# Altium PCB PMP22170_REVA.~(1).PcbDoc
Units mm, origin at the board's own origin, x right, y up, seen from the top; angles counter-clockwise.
Board outline 125.73 x 87.63 mm, 2 copper layers (Top Layer, Bottom Layer), stack 1.575 mm thick; 24 components, 0 nets, 16 pads, 0 vias.
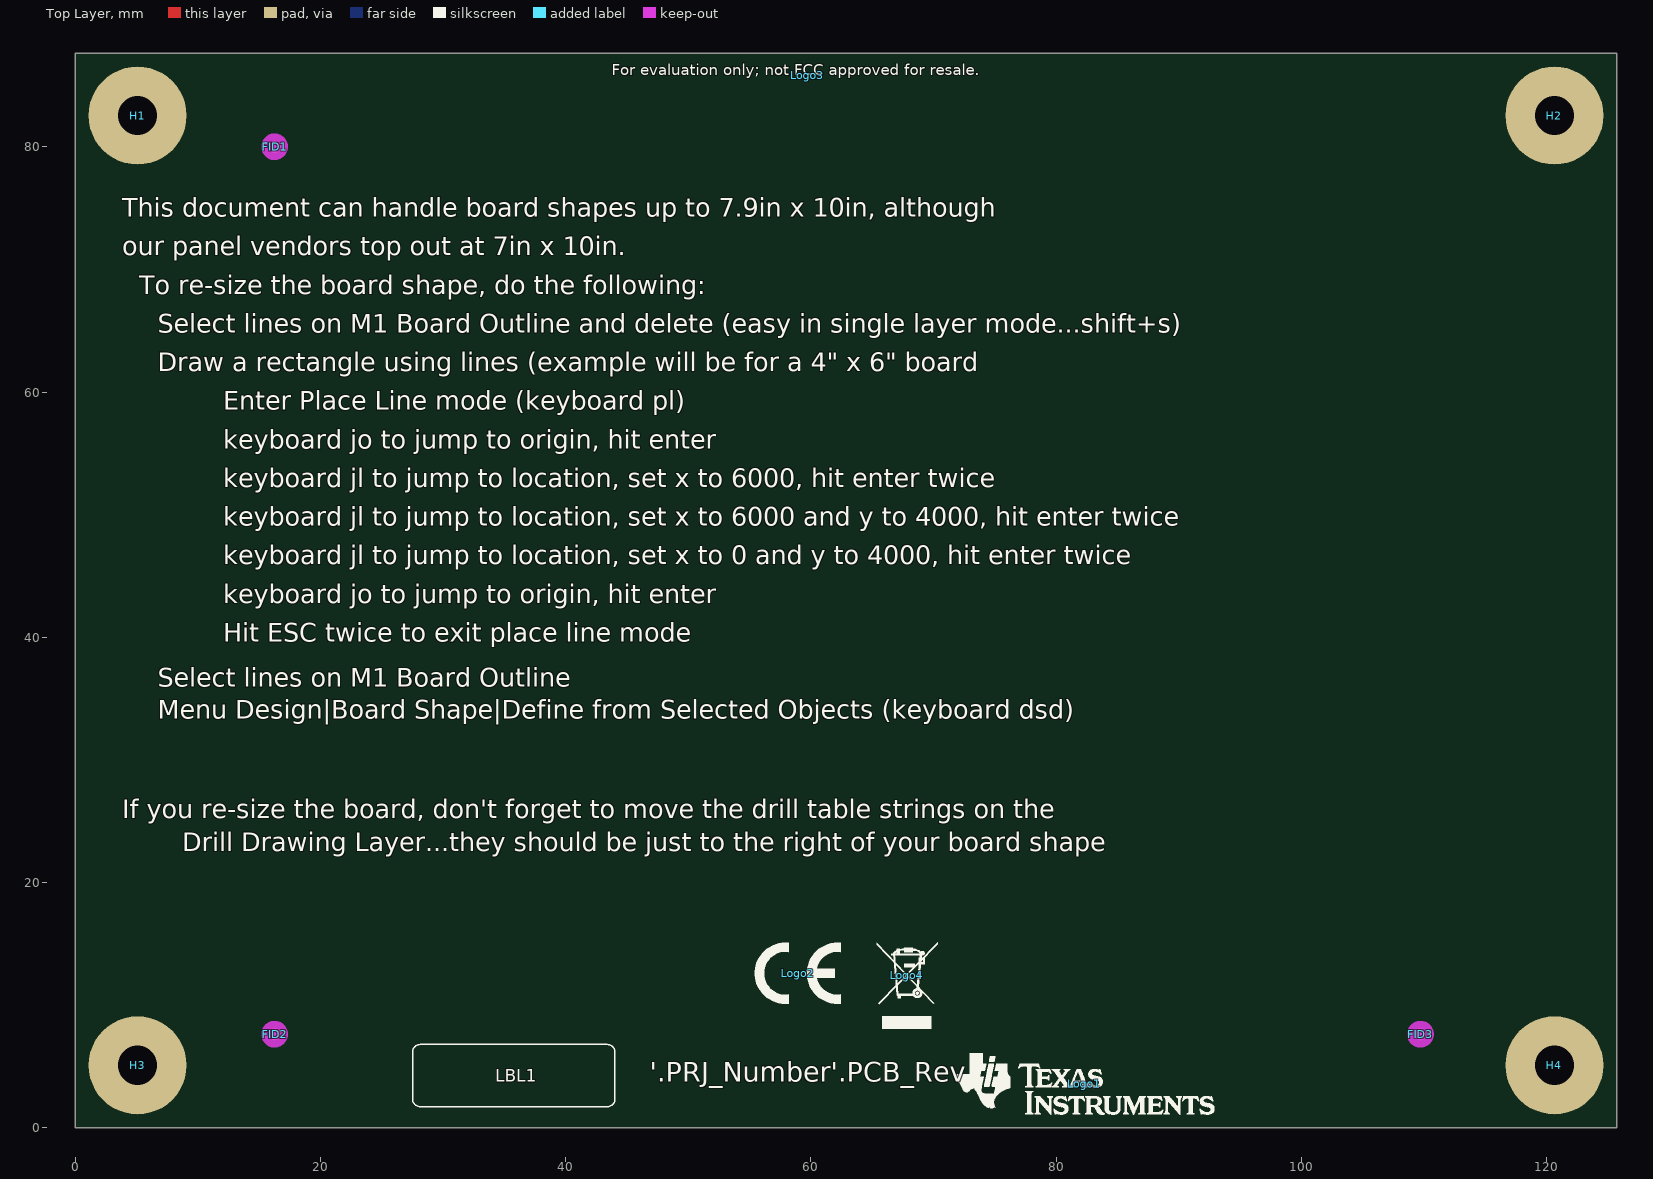
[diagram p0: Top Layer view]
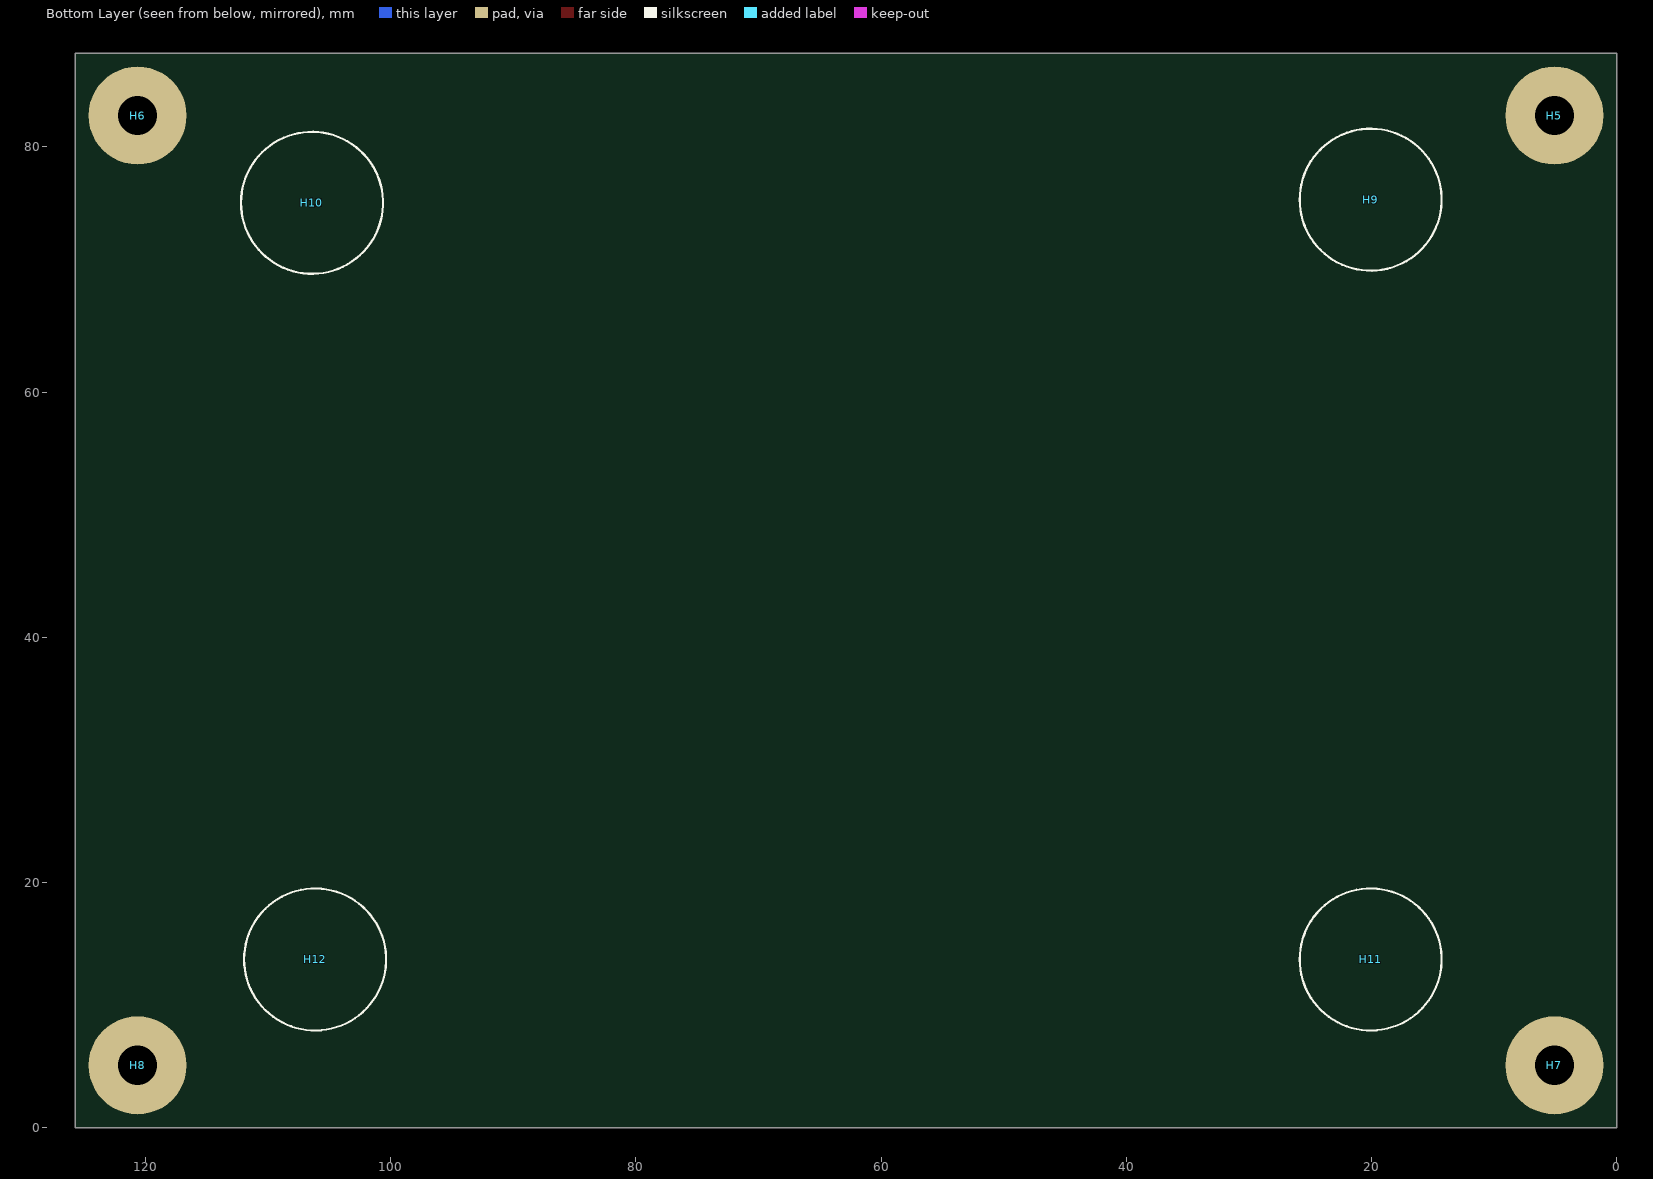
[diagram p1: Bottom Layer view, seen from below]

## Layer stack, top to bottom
Top Solder: solder mask 0.0102, Solder Resist, Dk 3.5
Top Layer: signal copper 0.0356
Dielectric1: core 1.5037, FR-4, Dk 4.8
Bottom Layer: signal copper 0.0356
Bottom Solder: solder mask 0.0102, Solder Resist, Dk 3.5

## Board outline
0,0 125.73,0 125.73,87.63 0,87.63

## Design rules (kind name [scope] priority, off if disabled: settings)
AcuteAngle [All] p1: minimum=4.50000000000000E+0001 checktracksonly=FALSE
AssemblyTestPointUsage [All] p1: valid=2
BoardOutlineClearance BoardOutlineClearance_MountingHoles [OnCopper and InComponentClass('Mounting Holes')] p1: gap=1 ignorepadtopadclearanceinfootprint=FALSE
BoardOutlineClearance BoardOutlineClearance_Poly [OnCopper and IsPoly] p2: gap=0.635 ignorepadtopadclearanceinfootprint=FALSE
BoardOutlineClearance [OnCopper and Not InComponentClass('Logo') and not InComponentClass('FiducialMark') and not InRegion(1000,500,4000,800) and not InPoly] p3: gap=1.905 ignorepadtopadclearanceinfootprint=FALSE
Clearance Clearance_Keepouts [((IsTrack Or IsArc) And Not InPoly) And IsFree and IsKeepOut vs ((IsTrack Or IsArc) And Not InPoly) And IsFree and IsKeepOut] p1: gap=0 ignorepadtopadclearanceinfootprint=FALSE
Clearance Clearance_Poly [InPolygon] p2: gap=0.635 ignorepadtopadclearanceinfootprint=TRUE
Clearance Clearance_FiducialMark [IsKeepOut and InComponentClass('FiducialMark') vs IsPad and InComponentClass('FiducialMark')] p3: gap=0 ignorepadtopadclearanceinfootprint=FALSE
Clearance [All] p4: gap=0.2 ignorepadtopadclearanceinfootprint=TRUE
ComponentClearance ComponentClearance_MountingHoles_FiducialMarks [InComponentClass('Mounting Holes') vs InComponentClass('FiducialMark')] p1: gap=1.27 collisioncheckmode=3 verticalgap=0.254 showdistances=FALSE
ComponentClearance ComponentClearance_Shunt [InComponentClass('Header') vs InComponentClass('Shunt')] p2: gap=0 collisioncheckmode=3 verticalgap=0 showdistances=FALSE
ComponentClearance ComponentClearance_Logo [InComponentClass('Logo')] p3: gap=1.27 collisioncheckmode=3 verticalgap=0.254 showdistances=FALSE
ComponentClearance ComponentClearance_ScrewToNut [(HasFootprint('NY PMS 440 0025 PH')) vs (HasFootprint('Keystone_1902C'))] p4: gap=0.127 collisioncheckmode=3 verticalgap=0.254 showdistances=FALSE
ComponentClearance ComponentClearance_MountingHoles [InComponentClass('Mounting Holes')] p5: gap=6.35 collisioncheckmode=3 verticalgap=2540 showdistances=FALSE
ComponentClearance ComponentClearance_SmallPassives [HasFootprint('0201*') or HasFootprint('0402*') or HasFootprint('0508') or HasFootprint('0603*') or HasFootprint('0612') or HasFootprint('0805*') or HasFootprint('0815*') or HasFootprint('0830*') or HasFootprint('1206*') or HasFootprint('1210*') or HasFootprint('1808*') or HasFootprint('1812*') or HasFootprint('1825*') or HasFootprint('2010*') or HasFootprint('2220*') or HasFootprint('2225*') or HasFootprint('2512*') or HasFootprint('2728*') or HasFootprint('3518*') vs HasFootprint('0201*') or HasFootprint('0402*') or HasFootprint('0508') or HasFootprint('0603*') or HasFootprint('0612') or HasFootprint('0805*') or HasFootprint('0815*') or HasFootprint('0830*') or HasFootprint('1206*') or HasFootprint('1210*') or HasFootprint('1808*') or HasFootprint('1812*') or HasFootprint('1825*') or HasFootprint('2010*') or HasFootprint('2220*') or HasFootprint('2225*') or HasFootprint('2512*') or HasFootprint('2728*') or HasFootprint('3518*')] p6: gap=0.38 collisioncheckmode=3 verticalgap=0.254 showdistances=FALSE
ComponentClearance ComponentClearance_THtoSMT [IsThruComponent vs IsSMTComponent] p7: gap=1.016 collisioncheckmode=3 verticalgap=0.762 showdistances=FALSE
ComponentClearance ComponentClearance_THtoTH [IsThruComponent vs IsThruComponent] p8: gap=0.762 collisioncheckmode=3 verticalgap=0.762 showdistances=FALSE
ComponentClearance [All] p9: gap=0.762 collisioncheckmode=3 verticalgap=0.254 showdistances=FALSE
DiffPairsRouting [All] p1: maxlimit=2.54 minlimit=0.254 mostfreqgap=0.254 toplayer_minwidth=0.381 toplayer_maxwidth=0.381 toplayer_prefwidth=0.381 bottomlayer_minwidth=0.381 bottomlayer_maxwidth=0.381 bottomlayer_prefwidth=0.381 maxuncoupledlength=25.4
FabricationTestPointUsage TestPointUsage [All] p1: valid=2 allowmultiple=FALSE
FabricationTestpoint Testpoint [All] p1: side=3 testpointundercomponent=TRUE minsize=1.016 maxsize=2.54 preferedsize=1.524 minholesize=0 maxholesize=1.016 preferedholesize=0.813 testpointgrid=0.025 allowsidetop=TRUE allowsidebottom=TRUE usegrid=TRUE gridtolerance=0
FanoutControl Fanout_LCC [IsLCC] p1: bgadir=Out bgaviamode=Centered fanoutstyle=Auto fanoutdirection=Alternating viagrid=0.025 // Fanout_LCC (Default Rule)
FanoutControl Fanout_BGA [IsBGA] p2: bgadir=Out bgaviamode=Centered fanoutstyle=Auto fanoutdirection=Alternating viagrid=0.025 // Fanout_BGA (Default Rule)
FanoutControl Fanout_Default [All] p4: bgadir=Out bgaviamode=Centered fanoutstyle=Auto fanoutdirection=Alternating viagrid=0.025 // Fanout_Default (Default Rule)
FanoutControl Fanout_Small [(CompPinCount < 5)] p5: bgadir=Out bgaviamode=Centered fanoutstyle=Auto fanoutdirection=OutThenIn viagrid=0.025 // Fanout_Small (Default Rule)
HoleSize [All] p1: absolutevalues=TRUE maxlimit=6.375 minlimit=0.2 maxpercent=80.000 minpercent=20.000
MinimumAnnularRing MinimumAnnularRing_ThermalPadVias [IsVia and InAnyComponent] p1: minimumring=0.15
MinimumAnnularRing [All] p2: minimumring=0.2
MinimumSolderMaskSliver MinimumSolderMaskSliver_Logo [InComponentClass('Logo') vs InComponentClass('Logo')] p1: minsoldermaskwidth=0.018
MinimumSolderMaskSliver [All] p2: minsoldermaskwidth=0.1
PlaneConnect [All] p1: planeconnectstyle=Relief reliefexpansion=0.254 reliefentries=4 reliefconductorwidth=0.254 reliefairgap=0.254
PolygonConnect [All] p1: connectstyle=Relief reliefconductorwidth=0.254 reliefentries=4 polygonreliefangle="90 Angle" airgapwidth=0.254
RoutingVias ThermalPadVias [IsVia and InAnyComponent] p1: holewidth=0.2 width=0.5 viastyle="Through Hole" minholewidth=0.2 minwidth=0.5 maxholewidth=0.33 maxwidth=0.6
RoutingVias [All] p2: holewidth=0.406 width=0.864 viastyle="Through Hole" minholewidth=0.2 minwidth=0.66 maxholewidth=1.016 maxwidth=1.651
SilkToBoardRegionClearance [Not ((IsComment or IsDesignator) And (Hide <> 'False')) and not InRegion(1000,500,4000,800)] p1:
SilkToSilkClearance SilkToSilkClearance_Pb-FreeLogo [(HasFootprint('Pb-Free_Overlay_Medium') OR HasFootprint('Pb-Free_Overlay_Small')) vs (HasFootprint('Pb-Free_Overlay_Medium') OR HasFootprint('Pb-Free_Overlay_Small'))] p1: silktosilkclearance=0
SilkToSilkClearance [All] p2: silktosilkclearance=0.1
SilkToSolderMaskClearance SilkToComponentPadClearance [(IsPad or IsFill or IsRegion) and InAnycomponent] p1: minsilkscreentomaskgap=0.127 clearancetoexposedcopper=TRUE
SilkToSolderMaskClearance "Silk to Solder Mask Opening" [All] p2: minsilkscreentomaskgap=0.1 clearancetoexposedcopper=FALSE
SolderMaskExpansion [All] p1: expansion=0.05
UnRoutedNet [All] p1: checkbadconnections=TRUE
Width [All] p1: maxlimit=2.54 minlimit=0.152 preferedwidth=0.254 checkconnectedcopper=TRUE
14 further rules are at their usual default settings.

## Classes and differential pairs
component class "Mounting Holes": H1 H2 H3 H4
component class Logo: Logo1
component class FiducialMark: FID1 FID2 FID3
component class AssemblyNote: ZZ1 ZZ2 ZZ3 ZZ4
component class Label: LBL1

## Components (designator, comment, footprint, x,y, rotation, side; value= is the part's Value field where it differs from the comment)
FID1 "Fiducial" Fiducial10-20 16.256,80.01 r0 top
FID2 "Fiducial" Fiducial10-20 16.256,7.62 r0 top
FID3 "Fiducial" Fiducial10-20 109.728,7.62 r0 top
H1 "NY PMS 440 0025 PH" "NY PMS 440 0025 PH" 5.08,82.55 r0 top locked
H2 "NY PMS 440 0025 PH" "NY PMS 440 0025 PH" 120.65,82.55 r0 top locked
H3 "NY PMS 440 0025 PH" "NY PMS 440 0025 PH" 5.08,5.08 r0 top locked
H4 "NY PMS 440 0025 PH" "NY PMS 440 0025 PH" 120.65,5.08 r0 top locked
H5 "1902C" Keystone_1902C 5.08,82.55 r180 bottom locked
H6 "1902C" Keystone_1902C 120.65,82.55 r180 bottom locked
H7 "1902C" Keystone_1902C 5.08,5.08 r180 bottom locked
H8 "1902C" Keystone_1902C 120.65,5.08 r180 bottom locked
H9 "SJ-5303 (CLEAR)" Bumpon_SJ5003Transparent 20.066,75.692 r180 bottom
H10 "SJ-5303 (CLEAR)" Bumpon_SJ5003Transparent 106.426,75.438 r180 bottom
H11 "SJ-5303 (CLEAR)" Bumpon_SJ5003Transparent 20.066,13.716 r180 bottom
H12 "SJ-5303 (CLEAR)" Bumpon_SJ5003Transparent 106.172,13.716 r180 bottom
LBL1 "THT-14-423-10" Label_650x200 35.763,4.242 r0 top
Logo1 "Texas Instruments" TI_Stacked_Overlay_Small 82.296,3.556 r0 top
Logo2 "CE Mark" CE_Mark_5mm 58.928,12.59 r0 top
Logo3 "FCC disclaimer" FCC_disclaimer 59.69,85.852 r0 top
Logo4 "WEEE logo" WEEE_Minimum 67.818,12.446 r0 top
ZZ1 "This Assembly Note is for PCB labels only" AssemblyNoteLabel 4.699,100.025 r0 top
ZZ2 "These assemblies are ESD sensitive, ESD precautions shall be observed." AssemblyNote 4.699,97.259 r0 top
ZZ3 "These assemblies must be clean and free from flux and all contaminants. Use of no clean flux is not acceptable." AssemblyNote 4.699,95.01 r0 top
ZZ4 "These assemblies must comply with workmanship standards IPC-A-610 Class 2, unless otherwise specified." AssemblyNote 4.699,92.761 r0 top

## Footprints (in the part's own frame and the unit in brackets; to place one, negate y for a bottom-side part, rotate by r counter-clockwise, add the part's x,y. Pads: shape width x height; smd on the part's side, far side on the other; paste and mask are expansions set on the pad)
AssemblyNote [mm] "Assembly Note"
AssemblyNoteLabel [mm] "Assembly Note for PCB Labels"
Bumpon_SJ5003Transparent [mil] "3M Hemispherical Bumpon transparent"
  round 1 on Mech4: 0(0,0)
  silkscreen extent -228,-228 228,228, body extent -219,-219 219,219, height 197
CE_Mark_5mm [mm] "Minimum text height for CE Mark"
  silkscreen extent -3.5,-2.5 3.5,2.5
FCC_disclaimer [mm]
Fiducial10-20 [mm]
  round 1 smd mask+0.5: 1(0,0)
  Top Layer keep-out circle w1.178: c0,0 r0.5
Keystone_1902C [mil] "Hex Standoff, 4-40 threaded, nylon"
  round 1 on Mech4: 0(0,0)
  body extent -145,-126 146,126, height 501
Label_650x200 [mil] "Thermal Transfer Label"
  round 1 on Mech13: 0(0,0)
  silkscreen extent -325,-100 325,100, body extent -325,-100 325,100, height 1
"NY PMS 440 0025 PH" [mm] "4-40 nylon screw and mounting hole"
  round 8 hole 3.2: 1(0,0)
  body extent -3.3,-3.3 3.3,3.3, height 2.69
TI_Stacked_Overlay_Small [mm]
  silkscreen extent -10.63,-2.49 10.63,2.49
WEEE_Minimum [mm] "WEEElie bin"
  silkscreen extent -2.42,-4.38 2.52,2.65

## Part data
FID1 FID2 FID3: library part CMP-0077181-1, "Fiducial mark.  There is nothing to buy or mount.", Manufacturer=N/A
H1 H2 H3 H4: library part CMP-0003617-1, "Machine Screw, Round, #4-40 x 1/4, Nylon, Philips panhead", Manufacturer="B&F Fastener Supply", Supplier Part Number 1=H542-ND
H5 H6 H7 H8: library part CMP-0003610-1, "Standoff, Hex, 0.5\"L #4-40 Nylon", Manufacturer=Keystone, Supplier Part Number 1=36-1902C-ND
H9 H10 H11 H12: library part CMP-0003620-1, "Bumpon, Hemisphere, 0.44 X 0.20, Clear", Manufacturer=3M, Supplier Part Number 1=SJ5303-7-ND
LBL1: library part CMP-0003625-1, "Thermal Transfer Printable Labels, 0.650\" W x 0.200\" H - 10,000 per roll", Manufacturer=Brady, Supplier Part Number 1=97C5133
Logo1: library part CMP-0074838-1, "Texas Instrument Corporate Signature"
Logo2: library part CMP-0074844-1
Logo3: library part CMP-0074847-1, "FCC_disclaimer"
Logo4: library part CMP-0074769-1
ZZ1: library part CMP-0003616-3
ZZ2: library part CMP-0077236-1
ZZ3: library part CMP-0077237-1
ZZ4: library part CMP-0077238-1

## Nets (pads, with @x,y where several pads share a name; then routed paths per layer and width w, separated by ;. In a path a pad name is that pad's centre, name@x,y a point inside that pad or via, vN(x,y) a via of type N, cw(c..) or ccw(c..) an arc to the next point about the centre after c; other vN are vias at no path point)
pads on no net: FID1.1 FID2.1 FID3.1 H1.1 H2.1 H3.1 H4.1 H5.0 H6.0 H7.0 H8.0 H9.0 H10.0 H11.0 H12.0 LBL1.0

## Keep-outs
Keep-Out Layer:
  text ".Layer_Name" at 14.656,-21.806 h1.52

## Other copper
Top Layer:
  text ".Layer_Name" at 14.656,-21.806 h1.52
Bottom Layer:
  text ".Layer_Name" at 14.656,-21.806 h1.52

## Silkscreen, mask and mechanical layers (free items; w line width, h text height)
Top Overlay:
  text "This document can handle board shapes up to 7.9in x 10in, although" at 3.81,74.295 h1.52
  text "our panel vendors top out at 7in x 10in." at 3.81,71.144 h1.52
  text "To re-size the board shape, do the following:" at 5.207,67.993 h1.52
  text "Select lines on M1 Board Outline and delete (easy in single layer mode...shift+s)" at 6.731,64.842 h1.52
  text "Draw a rectangle using lines (example will be for a 4\" x 6\" board" at 6.731,61.691 h1.52
  text "Enter Place Line mode (keyboard pl)" at 12.065,58.54 h1.52
  text "keyboard jo to jump to origin, hit enter" at 12.065,55.388 h1.52
  text "keyboard jl to jump to location, set x to 6000, hit enter twice" at 12.065,52.237 h1.52
  text "keyboard jl to jump to location, set x to 6000 and y to 4000, hit enter twice" at 12.065,49.086 h1.52
  text "keyboard jl to jump to location, set x to 0 and y to 4000, hit enter twice" at 12.065,45.935 h1.52
  text "keyboard jo to jump to origin, hit enter" at 12.065,42.784 h1.52
  text "Hit ESC twice to exit place line mode" at 12.065,39.633 h1.52
  text "Select lines on M1 Board Outline" at 6.731,35.974 h1.52
  text "Menu Design|Board Shape|Define from Selected Objects (keyboard dsd)" at 6.731,33.331 h1.52
  text "If you re-size the board, don't forget to move the drill table strings on the" at 3.81,25.222 h1.52
  text "Drill Drawing Layer...they should be just to the right of your board shape" at 8.712,22.53 h1.52
  text "'.PRJ_Number'.PCB_Rev" at 46.863,3.195 h2.75
  text ".Layer_Name" at 14.656,-21.806 h1.52
Bottom Overlay:
  text ".Layer_Name" at 14.656,-21.806 h1.52
Top Paste:
  text ".Layer_Name" at 14.656,-21.806 h1.52
Bottom Paste:
  text ".Layer_Name" at 14.656,-21.806 h1.52
Top Solder:
  text ".Layer_Name" at 14.656,-21.806 h1.52
  text ".Layer_Name" at 14.656,-21.806 h1.52
Bottom Solder:
  text ".Layer_Name" at 14.656,-21.806 h1.52
Drill Guide:
  text ".Layer_Name" at 14.656,-21.806 h1.52
M1 Board Outline:
  the board outline again, w0.254
  text ".Layer_Name" at 14.656,-21.806 h1.52
M2 Board Dimensions:
  rectangle: 0,-6.985 3.175,-3.81
  rectangle: 3.175,-10.16 12.7,-6.985
  lines w0.178: 0,-6.985 25.4,-6.985 ; 3.175,-10.16 3.175,-3.81 ; 6.35,-10.16 6.35,-3.81 ; 12.7,-10.16 12.7,-3.81 ; 19.05,-10.16 19.05,-3.81 ; 0,-10.16 25.4,-10.16 25.4,-3.81 0,-3.81 0,-10.16
  text ".Layer_Name" at 14.656,-21.806 h1.52
M3 3D STEP Top:
  text ".Layer_Name" at 14.656,-21.806 h1.52
M4 3D STEP Bottom:
  text ".Layer_Name" at 14.656,-21.806 h1.52
M5 Assembly Top:
  lines w0.254: -7.417,-23.626 160.223,-23.626 ; -7.417,-18.462 160.274,-18.462 ; -7.417,-13.297 -7.417,-28.791 94.31,-28.791 160.274,-28.791 160.274,-13.297 -7.404,-13.297 -7.404,-28.791 32.614,-28.791 ; 55.194,-28.791 55.194,-13.297 ; 87.376,-18.462 87.376,-13.297 ; 108.712,-18.462 108.712,-13.297 ; 124.511,-28.956 124.511,-23.804
  text "COMPONENTS MARKED 'DNP' SHOULD NOT BE POPULATED." at 29.299,-8.09 h1.52
  text "ASSEMBLY VARIANT:" at 29.286,-11.024 h1.52
  text ".VariantName" at 55.601,-11.024 h1.52
  text "PCB VIEWED FROM TOP SIDE" at -5.804,-16.654 h1.52
  text "BOARD #:" at 57.099,-16.654 h1.52
  text ".PRJ_Number" at 70.955,-16.654 h1.52
  text "REV:" at 92.405,-16.654 h1.52
  text ".PCB_Rev" at 99.809,-16.654 h1.52
  text "SVN REV:" at 113.69,-16.654 h1.52
  text ".VersionControl_RevNumber" at 126.543,-16.654 h1.52
  text "TID #:" at 57.099,-21.819 h1.52
  text ".TID" at 70.955,-21.819 h1.52
  text "PLOT NAME =" at -5.804,-27.034 h1.52
  text ".plot_File_Name" at 14.656,-27.034 h1.52
  text "GENERATED    :" at 57.15,-27.034 h1.52
  text ".Print_Date" at 79.235,-27.034 h1.52
  text ".Print_Time" at 97.752,-27.034 h1.52
  text "TEXAS INSTRUMENTS" at 129.87,-27.034 h1.52
M6 Assembly Bottom:
  lines w0.254: -7.429,-18.474 160.261,-18.474 ; -7.379,-23.639 160.261,-23.639 ; 28.334,-28.969 28.334,-23.817 ; 44.133,-18.474 44.133,-13.31 ; 65.468,-18.474 65.468,-13.31 ; 97.65,-28.804 97.65,-13.31 ; 120.231,-28.804 160.249,-28.804 160.249,-13.31 -7.429,-13.31 -7.429,-28.804 58.534,-28.804 160.261,-28.804 160.261,-13.31
  text "COMPONENTS MARKED 'DNP' SHOULD NOT BE POPULATED." at 154.991,-8.077 h1.52
  text ".VariantName" at 128.473,-11.024 h1.52
  text "ASSEMBLY VARIANT:" at 154.864,-11.024 h1.52
  text ".VersionControl_RevNumber" at 26.302,-16.667 h1.52
  text "SVN REV:" at 39.154,-16.667 h1.52
  text ".PCB_Rev" at 53.035,-16.667 h1.52
  text "REV:" at 60.439,-16.667 h1.52
  text ".PRJ_Number" at 81.89,-16.667 h1.52
  text "BOARD #:" at 95.745,-16.667 h1.52
  text "PCB VIEWED FROM BOTTOM SIDE" at 158.648,-16.667 h1.52
  text ".TID" at 81.89,-21.831 h1.52
  text "TID #:" at 95.745,-21.831 h1.52
  text "TEXAS INSTRUMENTS" at 22.974,-27.047 h1.52
  text ".Print_Time" at 55.093,-27.047 h1.52
  text ".Print_Date" at 73.609,-27.047 h1.52
  text "GENERATED    :" at 95.694,-27.047 h1.52
  text ".plot_File_Name" at 138.189,-27.047 h1.52
  text "PLOT NAME =" at 158.648,-27.047 h1.52
M9 Title Sheet:
  drawing of 57 lines, arcs and shapes, not listed
  text "1" at 18.792,204.127 h1.78
  text "2" at 82.182,204.127 h1.78
  text "3" at 145.411,204.127 h1.78
  text "4" at 209.08,204.127 h1.78
  text "5" at 272.555,204.127 h1.78
  text "6" at 336.182,204.127 h1.78
  text "A" at -10.579,175.095 h1.78
  text "A" at 365.341,175.095 h1.78
  text "B" at -10.579,114.643 h1.78
  text "B" at 365.341,114.643 h1.78
  text "C" at -10.579,54.318 h1.78
  text "C" at 365.341,54.318 h1.78
  text "PROJECT TITLE:" at 288.125,7.048 h1.14
  text ".PRJ_Title" at 289.395,3.662 h1.78
  text "DESIGNED FOR:" at 288.125,-0.597 h1.14
  text ".PRJ_Customer" at 289.395,-4.153 h1.78
  text "D" at -10.579,-5.88 h1.78
  text "D" at 365.341,-5.88 h1.78
  text "FILE NAME:" at 288.125,-8.217 h1.14
  text ".PCB_File_Name_No_Path" at 289.395,-11.265 h1.78
  text "Texas Instruments (TI) and/or its licensors do not warrant the accuracy or completeness of this specification" at 161.9,-15.376 h1.14
  text "ENGINEER:" at 288.125,-15.583 h1.14
  text "LAYOUT BY:" at 326.352,-15.583 h1.14
  text "or any information contained therein. TI and/or its licensors do not warrant that this design will meet" at 160.757,-18.237 h1.14
  text ".PRJ_Engineer" at 289.395,-19.52 h1.78
  text ".PCB_Layout" at 327.635,-19.52 h1.78
  text "the specifications, will be suitable for your application or fit for any particular purpose, or will operate in" at 160.757,-21.099 h1.14
  text ".Layer_Name" at 14.656,-21.806 h1.52
  text "ALTIUM DESIGNER VERSION:" at 326.352,-23.457 h1.14
  text "an implementation. TI and/or its licensors do not warrant that the design is production worthy. You should" at 160.757,-23.961 h1.14
  text "completely validate and test your design implementation to confirm the system functionality for your application." at 161.9,-26.822 h1.14
  text ".print_Scale" at 289.395,-26.843 h1.78
  text ".Application_BuildNumber" at 327.635,-26.843 h1.78
  text "1" at 18.792,-32.093 h1.78
  text "2" at 82.182,-32.093 h1.78
  text "3" at 145.411,-32.093 h1.78
  text "4" at 209.08,-32.093 h1.78
  text "5" at 272.555,-32.093 h1.78
  text "6" at 336.182,-32.093 h1.78
M10 Fab Notes:
  drawing of 189 lines, arcs and shapes, not listed
  text "DESIGN INFORMATION" at 314.503,161.447 h1.52
  text "MIN. TRACK WIDTH:" at 298.131,158.091 h1.52
  text "8" at 325.976,158.091 h1.52
  text "MIL" at 329.907,158.091 h1.52
  text "MIN. CLEARANCE:" at 298.131,154.938 h1.52
  text "0.2" at 324.452,154.938 h1.52
  text "mm" at 329.907,154.938 h1.52
  text "MIN. VIA PAD SIZE:" at 298.131,151.785 h1.52
  text "24" at 325.214,151.785 h1.52
  text "MIL" at 329.907,151.785 h1.52
  text "0.05mm (2MIL)" at 315.784,148.486 h1.52
  text "MINIMUM ANNULAR RING" at 289.769,148.277 h1.52
  text "EXTERNAL" at 333.768,148.277 h1.52
  text "PER" at 294.849,145.48 h1.52
  text "IPC-D-275 CLASS 2 LEVEL C" at 300.437,145.48 h1.52
  text "MIL, HOLES" at 338.238,142.928 h1.52
  text "+/-" at 328.27,142.709 h1.52
  text "+/-" at 349.961,142.709 h1.52
  text "REGISTRATION TOLERANCES:" at 289.769,142.682 h1.52
  text "METAL" at 320.243,142.682 h1.52
  text "5" at 334.879,142.683 h1.52
  text "3" at 356.037,142.683 h1.52
  text "MIL" at 358.99,142.682 h1.52
  text "HOLE SIZE TOLERANCE (UNLESS OTHERWISE SPECIFIED):" at 289.769,140.185 h1.52
  text "+/-" at 349.961,140.112 h1.52
  text "3" at 356.037,140.085 h1.52
  text "MIL" at 358.99,140.085 h1.52
  text "MATERIAL:" at 287.87,136.589 h1.52
  text "FR-4 High Tg" at 312.926,133.324 h1.52
  text "X" at 309.257,133.122 h1.52
  text "FR-408" at 298.563,133.007 h1.52
  text "OTHER" at 336.358,133.007 h1.52
  text "62 MIL (1.6mm) +/-10%" at 306.694,129.374 h1.52
  text "X" at 303.643,129.312 h1.52
  text "THICKNESS:" at 289.769,129.165 h1.52
  text "OTHER" at 339.33,129.165 h1.52
  text "TOLERANCE:" at 289.769,125.652 h1.52
  text "X" at 311.314,125.652 h1.52
  text "ANSI IPC-6012 TYPE 3 CLASS 2" at 315.836,125.652 h1.52
  text "OTHER +/-" at 315.835,121.989 h1.52
  text "BOW & TWIST:" at 289.769,118.302 h1.52
  text "X" at 311.314,118.302 h1.52
  text "ANSI IPC-6012 TYPE 3 CLASS 2" at 315.836,118.302 h1.52
  text "OTHER +/-" at 315.835,114.576 h1.52
  text "DRILLING:" at 287.87,111.258 h1.52
  text "NC_DRILL FILES" at 332.599,108.586 h1.52
  text "REFERENCE:" at 289.769,108.486 h1.52
  text "X" at 306.463,108.484 h1.52
  text "AS SHOWN" at 310.984,108.486 h1.52
  text "X" at 329.348,108.486 h1.52
  text "OTHER" at 340.168,104.873 h1.52
  text "PTH COPPER THICKNESS:" at 289.761,104.783 h1.52
  text "X" at 318.697,104.783 h1.52
  text "20-30 um" at 321.948,104.783 h1.52
  text "BOARD FINISH:" at 287.87,101.034 h1.52
  text "SILKSCREEN:" at 291.812,98.237 h1.52
  text "X" at 316.14,98.237 h1.52
  text "TOP" at 319.112,98.237 h1.52
  text "X" at 329.094,98.237 h1.52
  text "BOTTOM" at 332.091,98.237 h1.52
  text "SILKSCREEN COLOR:" at 291.812,94.295 h1.52
  text "X" at 316.115,94.295 h1.52
  text "WHITE" at 319.112,94.295 h1.52
  text "OTHER" at 332.091,94.295 h1.52
  text "X" at 319.442,90.652 h1.52
  text "GREEN" at 322.439,90.652 h1.52
  text "OTHER" at 338.136,90.652 h1.52
  text "SOLDER RESIST COLOR:" at 291.812,90.477 h1.52
  text "X" at 319.442,86.734 h1.52
  text "MATTE" at 322.439,86.734 h1.52
  text "SEMI-GLOSS" at 338.125,86.717 h1.52
  text "IMMERSION GOLD (ENIG)" at 314.819,82.345 h1.52
  text "ENEPIG" at 348.793,82.162 h1.52
  text "SURFACE FINISH:" at 287.87,82.136 h1.52
  text "X" at 310.298,82.136 h1.52
  text "IMM. TIN/SILVER OR EQUIV" at 296.24,78.649 h1.52
  text "OTHER" at 332.599,78.549 h1.52
  text "ARRAY/PANEL:" at 287.87,74.602 h1.52
  text "CUT AND TRIM PER M1 BOARD OUTLINE" at 314.819,74.393 h1.52
  text "N.C. ROUTE" at 314.819,70.94 h1.52
  text "X" at 332.295,70.94 h1.52
  text "V. SCORE" at 336.816,70.94 h1.52
  text "CERTIFICATION:" at 287.87,67.66 h1.52
  text "MATERIALS AND WORKMANSHIP FOR ALL PCBS" at 306.285,67.66 h1.52
  text "TO MEET OR EXCEED THE REQUIREMENTS OF:" at 306.285,65.271 h1.52
  text "X" at 297.078,62.003 h1.52
  text "ANSI IPC-A-600F CLASS ->" at 300.329,62.003 h1.52
  text "X" at 342.188,62.003 h1.52
  text "2" at 344.982,62.003 h1.52
  text "1" at 336.981,61.965 h1.52
  text "3" at 353.973,61.965 h1.52
  text "X" at 317.702,58.252 h1.52
  text "RoHS" at 320.953,58.252 h1.52
  text "OTHER" at 337.321,58.252 h1.52
  text "PER ORDER" at 347.407,58.252 h1.52
  text "ALL BOARDS MUST MEET OR EXCEED UL94-V0 REQUIREMENTS." at 288.569,54.345 h1.52
  text "PCB MUST BEAR THE UL94V-0 UL REGISTERED MATERIAL ID NUMBER" at 288.569,51.397 h1.52
  text "ADDITIONAL REQUIREMENTS:" at 287.87,47.094 h1.52
  text "MICROSECTION:" at 289.769,44.373 h1.52
  text "YES" at 312.775,44.373 h1.52
  text "REQUIRED" at 334.657,40.707 h1.52
  text "BARE BOARD ELEC. TEST:" at 289.769,40.634 h1.52
  text "NONE" at 322.935,40.634 h1.52
  text "X" at 331.66,40.634 h1.52
  text "PER ORDER" at 349.693,40.634 h1.52
  text "XX MIL VIAS REQUIRE NON-CONDUCTIVE FILL AND PLANARIZE" at 294.04,35.428 h1.5
  text "XX MIL VIAS REQUIRE CONDUCTIVE FILL AND PLANARIZE" at 294.243,32.787 h1.52
  text "OUTER XX MIL TRACES REQUIRE 50 OHM SINGLE-ENDED IMPEDANCE" at 294.218,28.637 h1.47
  text "LAYER 2 & 3 (INNER LAYERS) XX MIL WIDE, XX MIL SPACE / TRACES REQUIRE 100 OHM DIFFERENTIAL IMPEDANCE" at 294.015,22.65 h1.52
  text ".Layer_Name" at 14.656,-21.806 h1.52
M11 Gerber Information:
  lines w0.254: -7.417,-23.626 160.223,-23.626 ; -7.417,-18.462 160.274,-18.462 ; -7.417,-13.297 -7.417,-28.791 94.31,-28.791 160.274,-28.791 160.274,-13.297 -7.404,-13.297 -7.404,-28.791 32.614,-28.791 ; 55.194,-28.791 55.194,-13.297 ; 87.376,-18.462 87.376,-13.297 ; 108.712,-18.462 108.712,-13.297 ; 124.511,-28.956 124.511,-23.804
  text "ALL ARTWORK VIEWED FROM TOP SIDE" at -5.804,-16.654 h1.52
  text "BOARD #:" at 57.099,-16.654 h1.52
  text ".PRJ_Number" at 70.955,-16.654 h1.52
  text "REV:" at 92.405,-16.654 h1.52
  text ".PCB_Rev" at 99.809,-16.654 h1.52
  text "SVN REV:" at 113.69,-16.654 h1.52
  text ".VersionControl_RevNumber" at 126.543,-16.654 h1.52
  text "LAYER NAME =" at -5.804,-21.806 h1.52
  text "TID #:" at 57.099,-21.819 h1.52
  text ".TID" at 70.955,-21.819 h1.52
  text "PLOT NAME =" at -5.804,-27.034 h1.52
  text ".plot_File_Name" at 14.656,-27.034 h1.52
  text "GENERATED    :" at 57.15,-27.034 h1.52
  text ".Print_Date" at 79.235,-27.034 h1.52
  text ".Print_Time" at 97.752,-27.034 h1.52
  text "TEXAS INSTRUMENTS" at 129.87,-27.034 h1.52
M12 Stackup:
  drawing of 191 lines, arcs and shapes, not listed
  text "Layer" at 249.215,199.452 h1.52
  text "Name" at 259.626,199.452 h1.52
  text "Material" at 283.242,199.452 h1.52
  text "Thickness" at 305.08,199.452 h1.52
  text "Constant" at 321.586,199.452 h1.52
  text "Board Layer Stack" at 336.06,199.452 h1.52
  text "1" at 249.215,196.404 h1.52
  text "Top Overlay" at 259.626,196.404 h1.52
  text "2" at 249.215,193.356 h1.52
  text "Top Solder" at 259.626,193.356 h1.52
  text "Solder Resist" at 283.242,193.356 h1.52
  text "0.40mil" at 305.08,193.356 h1.52
  text "3.5" at 321.586,193.356 h1.52
  text "3" at 249.215,190.308 h1.52
  text "Top Layer" at 259.626,190.308 h1.52
  text "Copper" at 283.242,190.308 h1.52
  text "1.40mil" at 305.08,190.308 h1.52
  text "4" at 249.215,187.26 h1.52
  text "Dielectric1" at 259.626,187.26 h1.52
  text "FR-4" at 283.242,187.26 h1.52
  text "59.20mil" at 305.08,187.26 h1.52
  text "4.8" at 321.586,187.26 h1.52
  text "5" at 249.215,184.212 h1.52
  text "Bottom Layer" at 259.626,184.212 h1.52
  text "Copper" at 283.242,184.212 h1.52
  text "1.40mil" at 305.08,184.212 h1.52
  text "6" at 249.215,181.164 h1.52
  text "Bottom Solder" at 259.626,181.164 h1.52
  text "Solder Resist" at 283.242,181.164 h1.52
  text "0.40mil" at 305.08,181.164 h1.52
  text "3.5" at 321.586,181.164 h1.52
  text "7" at 249.215,178.116 h1.52
  text "Bottom Overlay" at 259.626,178.116 h1.52
  text ".Layer_Name" at 14.656,-21.806 h1.52
M13 Component Bodies Top:
  text ".Layer_Name" at 14.656,-21.806 h1.52
M14 Component Bodies Bottom:
  text ".Layer_Name" at 14.656,-21.806 h1.52
M15 Courtyards Top:
  text ".Layer_Name" at 14.656,-21.806 h1.52
M16 Courtyards Bottom:
  text ".Layer_Name" at 14.656,-21.806 h1.52
Drill Drawing:
  circle w0.254: c136.238,83.726 r0.702
  lines w0.305: 134.264,82.077 216.344,82.077 ; 134.264,85.234 216.344,85.234 ; 142.846,78.919 142.846,88.392 ; 151.279,78.919 151.279,88.392 ; 167.448,78.919 167.448,88.392 ; 174.03,78.919 174.03,88.392 ; 183.559,78.919 183.559,88.392 ; 201.957,78.919 201.957,88.392 ; 134.264,78.919 216.344,78.919 216.344,88.392 134.264,88.392 134.264,78.919
  text "Symbol" at 136.159,86.182 h1.83
  text "Quantity" at 143.793,86.182 h1.83
  text "Finished Hole Size" at 152.226,86.182 h1.83
  text "Plated" at 168.395,86.182 h1.83
  text "Hole Type" at 174.977,86.182 h1.83
  text "Drill Layer Pair" at 184.506,86.182 h1.83
  text "Hole Tolerance" at 202.904,86.182 h1.83
  text "4" at 143.793,83.024 h1.52
  text "125.98mil (3.200mm)" at 152.226,83.024 h1.52
  text "PTH" at 168.395,83.024 h1.52
  text "Round" at 174.977,83.024 h1.52
  text "Top Layer - Bottom Layer" at 184.506,83.024 h1.52
  text "4 Total" at 143.793,79.866 h1.52
  text ".Layer_Name" at 14.656,-21.806 h1.52
M17 Embedded Cavity:
  text ".Layer_Name" at 14.656,-21.806 h1.52
M18 Embedded Assembly:
  text ".Layer_Name" at 14.656,-21.806 h1.52
M19 Embedded Keepout:
  text ".Layer_Name" at 14.656,-21.806 h1.52

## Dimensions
0,-10.16 to 25.4,-10.16 on M2 Board Dimensions
0,0 to 0,87.63 on M2 Board Dimensions
0,0 to 125.73,0 on M2 Board Dimensions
